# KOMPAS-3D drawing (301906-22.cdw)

Views: Вид 1, Вид 2, Вид 3, Вид 4
Referenced files: ребро опоры.cdw
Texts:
  Ребро опоры
  денис
  Текст на чертеже
  Размерные надписи
  Шероховатость
  Линия-выноска #1
  Линия-выноска #2
  Линия-выноска #3
  Отклонения формы и база
  Заголовок таблицы
  Ячейка таблицы
  Стрелка вида
  Обозначение изменения
  Фигурная скобка
  Номер узла
  Марка координационной оси
  VRCB
  Выносная надпись
  Обозначение узла
  Марка/позиционное обозначение с линией-выноской
  Марка/позиционное обозначение на линии
  Марка/позиционное обозначение без линии-выноски
  Баранов Д.А.
  СПбГТИ(ТУ)
  гр.364
  Сталь 12Х18Н10Т  Лист
Dimensions and other numbers on the sheet: 05.16.01.01.000; 7; 525; 320; 173,02; 45; 8; 1:7; 1; 05.16.01.01.000-; 0; 2; 3; 4; 5; 6; 9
